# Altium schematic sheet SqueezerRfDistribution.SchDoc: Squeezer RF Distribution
size C; Organization: LIGO Laboratory; Address1: California Institute of Technology; Address2: Massachusetts Institute of Technology; SheetNumber: 31; SheetTotal: 37; DrawnBy: R.  Abbott; Engineer: R.  Abbott
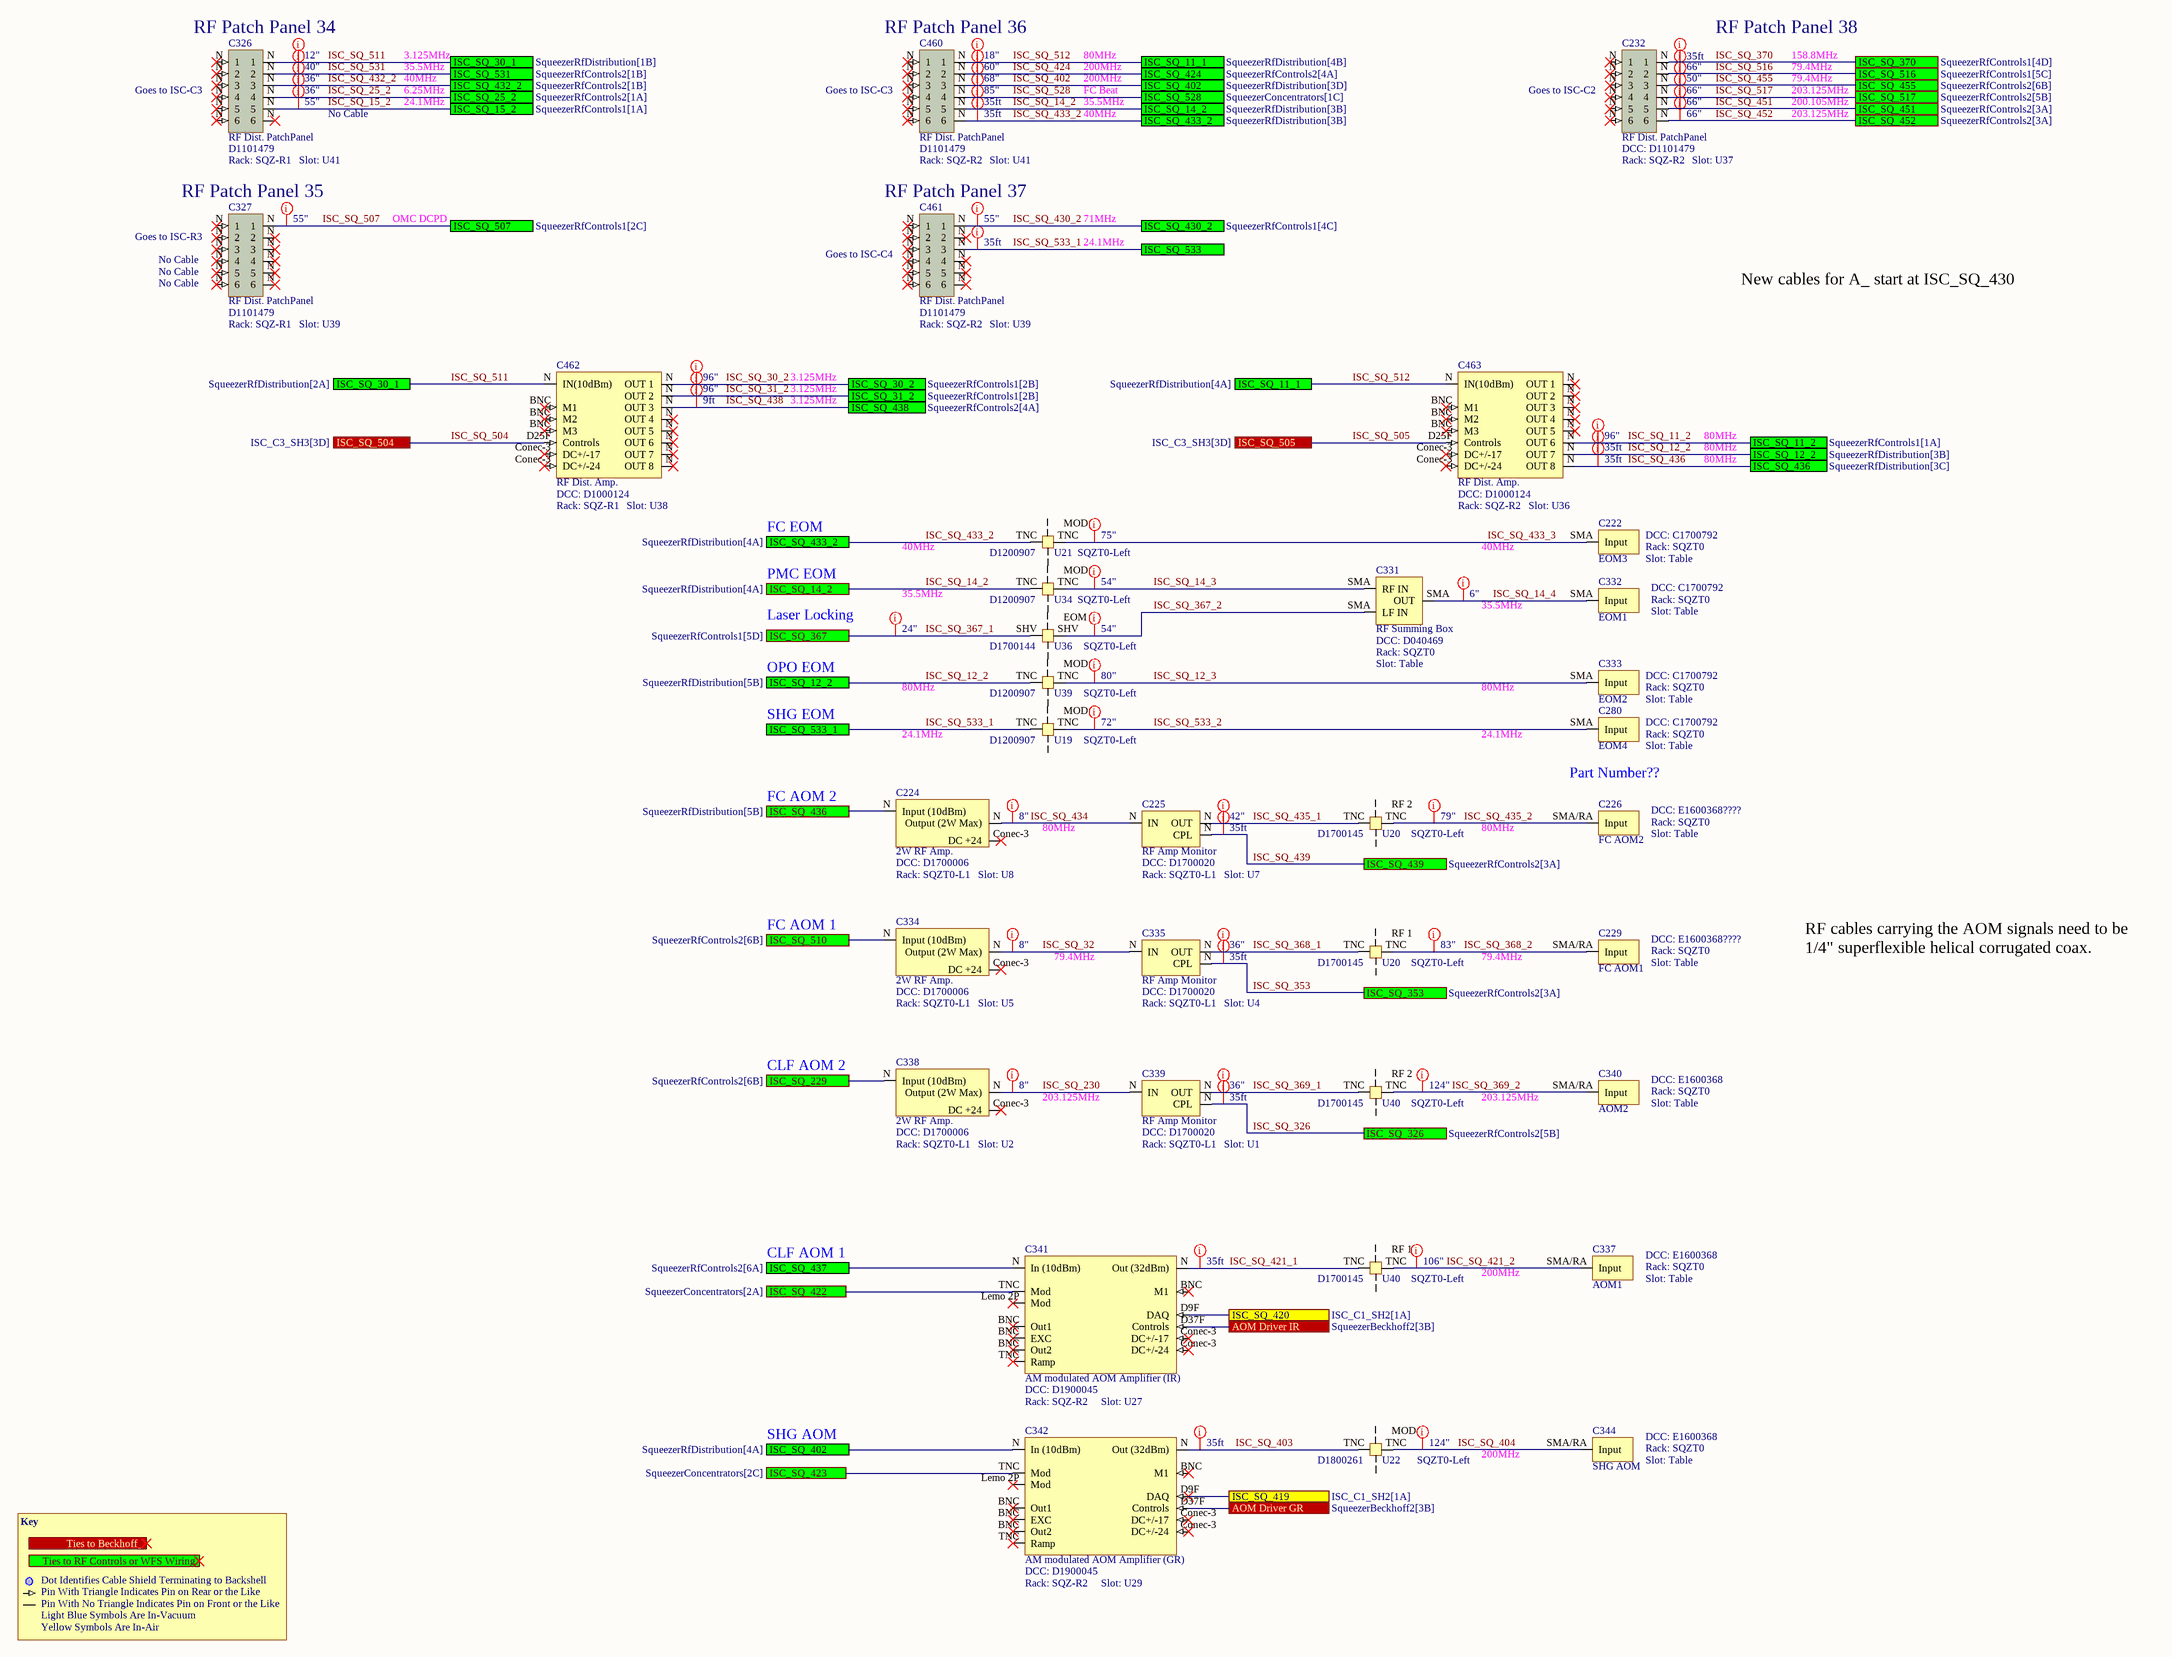
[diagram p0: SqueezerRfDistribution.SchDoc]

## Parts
C218  DCC: D1700144  Rack: SQZT0-Left  Slot: U36  (hidden comment: Patch Panel Laser Locking)  (part B of 4)
C222  EOM3  DCC: C1700792  Rack: SQZT0  Slot: Table
C223  DCC: D1200907  Rack: SQZT0-Left  Slot: U21  (hidden comment: Patch Panel Modulator)
C224  2W RF Amp.  DCC: D1700006  Rack: SQZT0-L1  Slot: U8
C225  RF Amp Monitor  DCC: D1700020  Rack: SQZT0-L1  Slot: U7
C226  FC AOM2  DCC: E1600368????  Rack: SQZT0  Slot: Table
C227  DCC: D1700145  Rack: SQZT0-Left  Slot: U20  (hidden comment: Patch Panel AOM)  (parts A,B of 2)
C229  FC AOM1  DCC: E1600368????  Rack: SQZT0  Slot: Table
C232  RF Dist. PatchPanel  DCC: D1101479  Rack: SQZ-R2  Slot: U37
C280  EOM4  DCC: C1700792  Rack: SQZT0  Slot: Table
C286  DCC: D1200907  Rack: SQZT0-Left  Slot: U19  (hidden comment: Patch Panel Modulator)
C326  RF Dist. PatchPanel  DCC: D1101479  Rack: SQZ-R1  Slot: U41
C327  RF Dist. PatchPanel  DCC: D1101479  Rack: SQZ-R1  Slot: U39
C328  DCC: D1200907  Rack: SQZT0-Left  Slot: U34  (hidden comment: Patch Panel Modulator)
C330  DCC: D1200907  Rack: SQZT0-Left  Slot: U39  (hidden comment: Patch Panel Modulator)
C331  RF Summing Box  DCC: D040469  Rack: SQZT0  Slot: Table
C332  EOM1  DCC: C1700792  Rack: SQZT0  Slot: Table
C333  EOM2  DCC: C1700792  Rack: SQZT0  Slot: Table
C334  2W RF Amp.  DCC: D1700006  Rack: SQZT0-L1  Slot: U5
C335  RF Amp Monitor  DCC: D1700020  Rack: SQZT0-L1  Slot: U4
C336  DCC: D1700145  Rack: SQZT0-Left  Slot: U40  (hidden comment: Patch Panel AOM)  (parts A,B of 2)
C337  AOM1  DCC: E1600368  Rack: SQZT0  Slot: Table
C338  2W RF Amp.  DCC: D1700006  Rack: SQZT0-L1  Slot: U2
C339  RF Amp Monitor  DCC: D1700020  Rack: SQZT0-L1  Slot: U1
C340  AOM2  DCC: E1600368  Rack: SQZT0  Slot: Table
C341  AM modulated AOM Amplifier (IR)  DCC: D1900045  Rack: SQZ-R2  Slot: U27
C342  AM modulated AOM Amplifier (GR)  DCC: D1900045  Rack: SQZ-R2  Slot: U29
C343  DCC: D1800261  Rack: SQZT0-Left  Slot: U22  (hidden comment: Patch Panel Amplitude Modulator)
C344  SHG AOM  DCC: E1600368  Rack: SQZT0  Slot: Table
C460  RF Dist. PatchPanel  DCC: D1101479  Rack: SQZ-R2  Slot: U41
C461  RF Dist. PatchPanel  DCC: D1101479  Rack: SQZ-R2  Slot: U39
C462  RF Dist. Amp.  DCC: D1000124  Rack: SQZ-R1  Slot: U38
C463  RF Dist. Amp.  DCC: D1000124  Rack: SQZ-R2  Slot: U36

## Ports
AOM Driver GR (see SqueezerBeckhoff2[3B]), AOM Driver IR (see SqueezerBeckhoff2[3B]), ISC_SQ_11_1 (see SqueezerRfDistribution[4A]), ISC_SQ_11_1 (see SqueezerRfDistribution[4B]), ISC_SQ_11_2 (see SqueezerRfControls1[1A]), ISC_SQ_12_2 (see SqueezerRfDistribution[3B]), ISC_SQ_12_2 (see SqueezerRfDistribution[5B]), ISC_SQ_14_2 (see SqueezerRfDistribution[3B]), ISC_SQ_14_2 (see SqueezerRfDistribution[4A]), ISC_SQ_15_2 (see SqueezerRfControls1[1A]), ISC_SQ_25_2 (see SqueezerRfControls2[1A]), ISC_SQ_30_1 (see SqueezerRfDistribution[1B]), ISC_SQ_30_1 (see SqueezerRfDistribution[2A]), ISC_SQ_30_2 (see SqueezerRfControls1[2B]), ISC_SQ_31_2 (see SqueezerRfControls1[2B]), ISC_SQ_229 (see SqueezerRfControls2[6B]), ISC_SQ_326 (see SqueezerRfControls2[5B]), ISC_SQ_353 (see SqueezerRfControls2[3A]), ISC_SQ_367 (see SqueezerRfControls1[5D]), ISC_SQ_370 (see SqueezerRfControls1[4D]), ISC_SQ_402 (see SqueezerRfDistribution[3D]), ISC_SQ_402 (see SqueezerRfDistribution[4A]), ISC_SQ_419 (see ISC_C1_SH2[1A]), ISC_SQ_420 (see ISC_C1_SH2[1A]), ISC_SQ_422 (see SqueezerConcentrators[2A]), ISC_SQ_423 (see SqueezerConcentrators[2C]), ISC_SQ_424 (see SqueezerRfControls2[4A]), ISC_SQ_430_2 (see SqueezerRfControls1[4C]), ISC_SQ_432_2 (see SqueezerRfControls2[1B]), ISC_SQ_433_2 (see SqueezerRfDistribution[3B]), ISC_SQ_433_2 (see SqueezerRfDistribution[4A]), ISC_SQ_436 (see SqueezerRfDistribution[3C]), ISC_SQ_436 (see SqueezerRfDistribution[5B]), ISC_SQ_437 (see SqueezerRfControls2[6A]), ISC_SQ_438 (see SqueezerRfControls2[4A]), ISC_SQ_439 (see SqueezerRfControls2[3A]), ISC_SQ_451 (see SqueezerRfControls2[3A]), ISC_SQ_452 (see SqueezerRfControls2[3A]), ISC_SQ_455 (see SqueezerRfControls2[6B]), ISC_SQ_504 (see ISC_C3_SH3[3D]), ISC_SQ_505 (see ISC_C3_SH3[3D]), ISC_SQ_507 (see SqueezerRfControls1[2C]), ISC_SQ_510 (see SqueezerRfControls2[6B]), ISC_SQ_516 (see SqueezerRfControls1[5C]), ISC_SQ_517 (see SqueezerRfControls2[5B]), ISC_SQ_528 (see SqueezerConcentrators[1C]), ISC_SQ_531 (see SqueezerRfControls2[1B]), ISC_SQ_533, ISC_SQ_533_1, Ties to Beckhoff_, Ties to RF Controls or WFS Wiring

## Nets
AOM Driver GR: C342.D37F(Controls) ; port AOM Driver GR
AOM Driver IR: C341.D37F(Controls) ; port AOM Driver IR
ISC_SQ_11_2: C463.N(OUT_6) ; port ISC_SQ_11_2
ISC_SQ_12_2: C330.TNC C463.N(OUT_7) ; port ISC_SQ_12_2
ISC_SQ_12_3: C330.TNC C333.SMA(Input)
ISC_SQ_14_2: C328.TNC C460.N(5) ; port ISC_SQ_14_2
ISC_SQ_14_3: C328.TNC C331.SMA(RF_IN)
ISC_SQ_14_4: C331.SMA(OUT) C332.SMA(Input)
ISC_SQ_15_2: C326.N(5) ; port ISC_SQ_15_2
ISC_SQ_25_2: C326.N(4) ; port ISC_SQ_25_2
ISC_SQ_30_2: C462.N(OUT_1) ; port ISC_SQ_30_2
ISC_SQ_31_2: C462.N(OUT_2) ; port ISC_SQ_31_2
ISC_SQ_32: C334.N(Output_(2W_Max)) C335.N(IN)
ISC_SQ_229: C338.N(Input_(10dBm)) ; port ISC_SQ_229
ISC_SQ_230: C338.N(Output_(2W_Max)) C339.N(IN)
ISC_SQ_326: C339.N(CPL) ; port ISC_SQ_326
ISC_SQ_353: C335.N(CPL) ; port ISC_SQ_353
ISC_SQ_367_1: C218.SHV(EOM) ; port ISC_SQ_367
ISC_SQ_367_2: C218.SHV(EOM) C331.SMA(LF_IN)
ISC_SQ_368_1: C227.TNC(RF1) C335.N(OUT)
ISC_SQ_368_2: C227.TNC(RF1) C229.SMA/RA(Input)
ISC_SQ_369_1: C336.TNC(RF2) C339.N(OUT)
ISC_SQ_369_2: C336.TNC(RF2) C340.SMA/RA(Input)
ISC_SQ_370: C232.N(1) ; port ISC_SQ_370
ISC_SQ_402: C342.N(In_(10dBm)) C460.N(3) ; port ISC_SQ_402
ISC_SQ_403: C342.N(Out_(32dBm)) C343.TNC
ISC_SQ_404: C343.TNC C344.SMA/RA(Input)
ISC_SQ_419: C342.D9F(DAQ) ; port ISC_SQ_419
ISC_SQ_420: C341.D9F(DAQ) ; port ISC_SQ_420
ISC_SQ_421_1: C336.TNC(RF1) C341.N(Out_(32dBm))
ISC_SQ_421_2: C336.TNC(RF1) C337.SMA/RA(Input)
ISC_SQ_422: C341.TNC(Mod) ; port ISC_SQ_422
ISC_SQ_423: C342.TNC(Mod) ; port ISC_SQ_423
ISC_SQ_424: C460.N(2) ; port ISC_SQ_424
ISC_SQ_430_2: C461.N(1) ; port ISC_SQ_430_2
ISC_SQ_432_2: C326.N(3) ; port ISC_SQ_432_2
ISC_SQ_433_2: C223.TNC C460.N(6) ; port ISC_SQ_433_2
ISC_SQ_433_3: C222.SMA(Input) C223.TNC
ISC_SQ_434: C224.N(Output_(2W_Max)) C225.N(IN)
ISC_SQ_435_1: C225.N(OUT) C227.TNC(RF2)
ISC_SQ_435_2: C226.SMA/RA(Input) C227.TNC(RF2)
ISC_SQ_436: C224.N(Input_(10dBm)) C463.N(OUT_8) ; port ISC_SQ_436
ISC_SQ_437: C341.N(In_(10dBm)) ; port ISC_SQ_437
ISC_SQ_438: C462.N(OUT_3) ; port ISC_SQ_438
ISC_SQ_439: C225.N(CPL) ; port ISC_SQ_439
ISC_SQ_451: C232.N(5) ; port ISC_SQ_451
ISC_SQ_452: C232.N(6) ; port ISC_SQ_452
ISC_SQ_455: C232.N(3) ; port ISC_SQ_455
ISC_SQ_504: C462.D25F(Controls) ; port ISC_SQ_504
ISC_SQ_505: C463.D25F(Controls) ; port ISC_SQ_505
ISC_SQ_507: C327.N(1) ; port ISC_SQ_507
ISC_SQ_510: C334.N(Input_(10dBm)) ; port ISC_SQ_510
ISC_SQ_511: C326.N(1) C462.N(IN(10dBm)) ; port ISC_SQ_30_1
ISC_SQ_512: C460.N(1) C463.N(OUT_1) ; port ISC_SQ_11_1
ISC_SQ_516: C232.N(2) ; port ISC_SQ_516
ISC_SQ_517: C232.N(4) ; port ISC_SQ_517
ISC_SQ_528: C460.N(4) ; port ISC_SQ_528
ISC_SQ_531: C326.N(2) ; port ISC_SQ_531
ISC_SQ_533_1: C286.TNC C461.N(3) ; port ISC_SQ_533, port ISC_SQ_533_1
ISC_SQ_533_2: C280.SMA(Input) C286.TNC

Not connected (* = marked no-connect by the designer): C224 Conec-3(DC_+24)*; C334 Conec-3(DC_+24)*; C338 Conec-3(DC_+24)*; C341 BNC(M1)* Conec-3(DC+/-17)* Lemo 2P(Mod)*; C342 BNC(M1)* Conec-3(DC+/-17)* Lemo 2P(Mod)*; C462 BNC(M1)* Conec-3(DC+/-17)*; C463 BNC(M1)* Conec-3(DC+/-17)*

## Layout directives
Length: 8": ISC_SQ_32, ISC_SQ_230, ISC_SQ_434
Length: 54": ISC_SQ_14_3, ISC_SQ_367_2
Length: 24": ISC_SQ_367_1
Length: 6": ISC_SQ_14_4
Length: 80": ISC_SQ_12_3
Length: 36": ISC_SQ_25_2, ISC_SQ_368_1, ISC_SQ_369_1, ISC_SQ_432_2
Length: 35ft: ISC_SQ_12_2, ISC_SQ_14_2, ISC_SQ_326, ISC_SQ_353, ISC_SQ_370, ISC_SQ_403, ISC_SQ_421_1, ISC_SQ_433_2, ISC_SQ_436, ISC_SQ_439, ISC_SQ_533_1
Length: 106": ISC_SQ_421_2
Length: 124": ISC_SQ_369_2, ISC_SQ_404
Length: 55": ISC_SQ_15_2, ISC_SQ_430_2, ISC_SQ_507
Length: 18": ISC_SQ_512
Length: 12": ISC_SQ_511
Length: 60": ISC_SQ_424
Length: 68": ISC_SQ_402
Length: 96": ISC_SQ_11_2, ISC_SQ_30_2, ISC_SQ_31_2
Length: 75": ISC_SQ_433_3
Length: 42": ISC_SQ_435_1
Length: 79": ISC_SQ_435_2
Length: 83": ISC_SQ_368_2
Length: 9ft: ISC_SQ_438
Length: 66": ISC_SQ_451, ISC_SQ_452, ISC_SQ_516, ISC_SQ_517
Length: 50": ISC_SQ_455
Length: 85": ISC_SQ_528
Length: 40": ISC_SQ_531
Length: 72": ISC_SQ_533_2

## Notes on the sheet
- (near C326) RF Patch Panel 34
- 3.125MHz
- 35.5MHz
- (near C460) RF Patch Panel 36
- 80MHz
- 200MHz
- (near C232) RF Patch Panel 38
- 158.8MHz
- 79.4MHz
- (near C326) Goes to ISC-C3
- No Cable
- 6.25MHz
- 40MHz
- 24.1MHz
- (near C460) Goes to ISC-C3
- FC Beat
- (near C232) Goes to ISC-C2
- 203.125MHz
- 200.105MHz
- (near C327) Goes to ISC-R3
- (near C327) RF Patch Panel 35
- OMC DCPD
- (near C461) RF Patch Panel 37
- 71MHz
- (near C327) No Cable
- (near C461) Goes to ISC-C4
- New cables for A_ start at ISC_SQ_430
- FC EOM
- PMC EOM
- Laser Locking
- OPO EOM
- SHG EOM
- Part Number??
- FC AOM 2
- FC AOM 1
- RF cables carrying the AOM signals need to be
  1/4" superflexible helical corrugated coax.
- CLF AOM 2
- CLF AOM 1
- SHG AOM
- Key
- Dot Identifies Cable Shield Terminating to Backshell
- Pin With Triangle Indicates Pin on Rear or the Like
- Pin With No Triangle Indicates Pin on Front or the Like
- Light Blue Symbols Are In-Vacuum
- Yellow Symbols Are In-Air

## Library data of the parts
C218 = Patch Panel Laser Locking: Patch Panel (D1700144); Serial: Sxxxxxxx; System: ISC
C222 C280 C332 C333 = EOM: Serial: Sxxxxxxx; System: ISC
C223 C286 C328 C330 = Patch Panel Modulator: Patch Panel (D1200907); Serial: Sxxxxxxx; System: ISC
C224 C334 C338 = 2W RF Amp.: Serial: Sxxxxxxx; System: ISC; Frequency: 200MHz
C225 C335 C339 = RF Amp Monitor: Serial: Sxxxxxxx; System: ISC
C226 C229 C337 C340 C344 = AOM: Serial: Sxxxxxxx; System: ISC
C227 C336 = Patch Panel AOM: Patch Panel (D1700145); Serial: Sxxxxxxx; System: ISC
C232 C326 C327 C460 C461 = RF Dist. PatchPanel: Serial: Sxxxxxxx; System: ISC
C331 = RF Summing Box: Serial: Sxxxxxxx; System: ISC
C341 C342 = AM AOM V2: AM AOM; Serial: Sxxxxxxx; System: SQZ
C343 = Patch Panel Amplitude Modulator: Patch Panel (D1800261); Serial: Sxxxxxxx; System: ISC
C462 C463 = RF Distribution Amplifier: Serial: Sxxxxxxx; System: ISC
